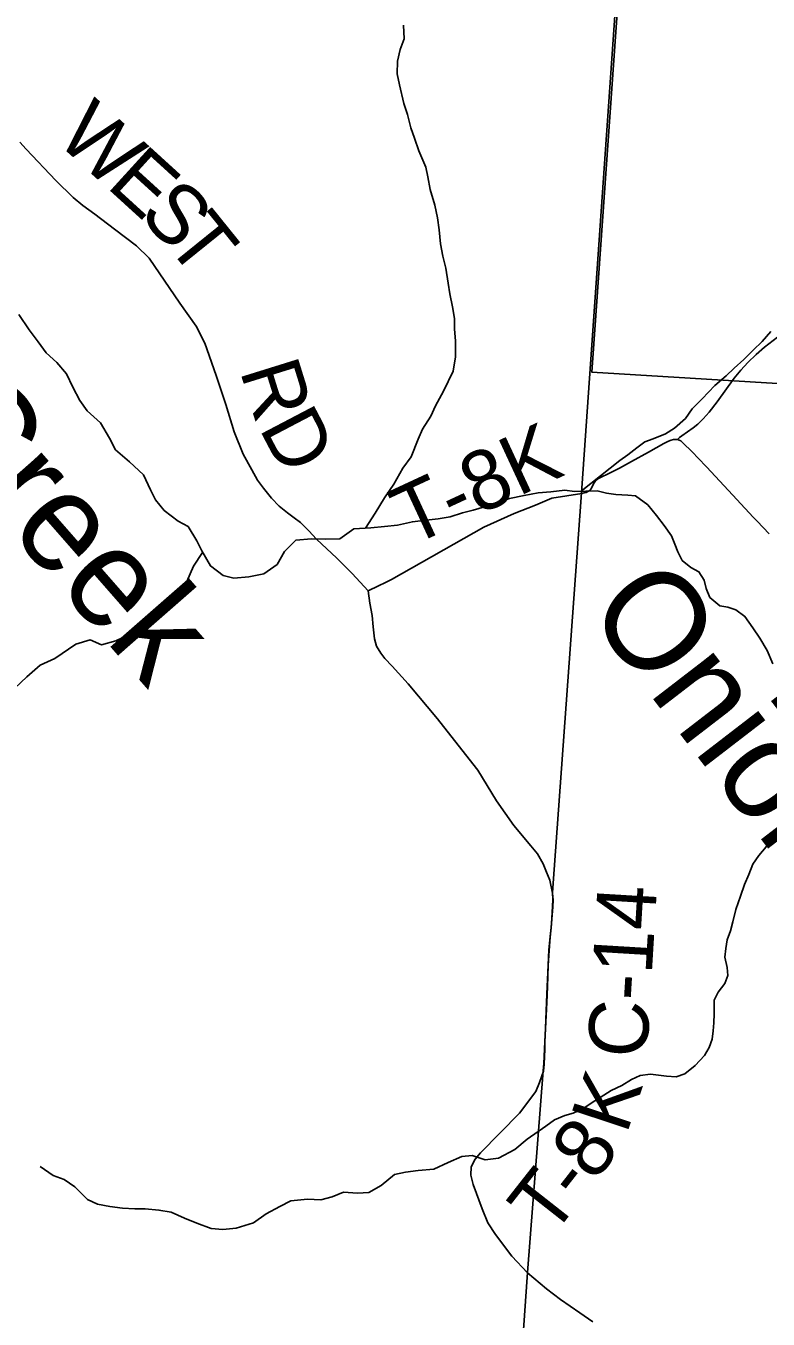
# Model space of a CAD drawing. Extents: x -8.2 to 34, y 0 to 22.
# Drawn here: x 6.05 to 6.76, y 18.744 to 19.98 of the extents above; entities that cross this region are included whole.
import ezdxf

# ---------------------------------------------------------------- set-up
doc = ezdxf.new("R2010")
doc.units = 0
for name, color, linetype in [('GM_X_Corporation', 7, 'Continuous'), ('GM_X_County_Road', 7, 'Continuous'), ('GM_X_County_Road_Text', 7, 'Continuous'), ('GM_X_Minor_River', 7, 'Continuous'), ('GM_X_Minor_River_Text', 7, 'Continuous'), ('GM_X_Township_Road', 7, 'Continuous'), ('GM_X_Township_Road_Text', 7, 'Continuous'), ('GM_X_Township_Text', 7, 'Continuous')]:
    doc.layers.add(name, color=color, linetype=linetype)

msp = doc.modelspace()

# ---------------------------------------------------------------- linework, layer by layer
at = {"layer": 'GM_X_Corporation'}
msp.add_lwpolyline([(6.4774, 18.0203), (6.488, 18.1752), (6.5242, 18.7061), (6.5297, 18.7882), (6.5448, 18.981), (6.5455, 18.9878), (6.5461, 19.0017), (6.5463, 19.009), (6.5469, 19.0218), (6.548, 19.0467), (6.5487, 19.0617), (6.5495, 19.0821), (6.5503, 19.0966), (6.5514, 19.1092), (6.5523, 19.118), (6.5529, 19.1264), (6.5537, 19.1382), (6.5541, 19.1447), (6.5536, 19.1514), (6.5814, 19.5334), (6.6608, 20.6695), (6.6768, 20.9), (2.1, 20.9), (2.1, 14.1)], dxfattribs=at)
msp.add_lwpolyline([(6.6629, 20.6653), (7.6877, 20.6096), (7.6147, 19.5864), (6.5914, 19.6487)], close=True, dxfattribs=at)
at = {"layer": 'GM_X_County_Road'}
for points in [[(6.0444, 19.8687), (6.0505, 19.8619), (6.0787, 19.832), (6.0954, 19.8159), (6.1045, 19.8081), (6.116, 19.7999), (6.135, 19.7855), (6.1558, 19.7696), (6.168, 19.7577), (6.1973, 19.7147), (6.2131, 19.6929), (6.2212, 19.6764), (6.232, 19.6455), (6.2415, 19.618), (6.2493, 19.5919), (6.2578, 19.5703), (6.2661, 19.5553), (6.2718, 19.5456), (6.2773, 19.5379), (6.2851, 19.5282), (6.2925, 19.5208), (6.3004, 19.5142), (6.3067, 19.5096), (6.3127, 19.5051), (6.3207, 19.4971), (6.3281, 19.489), (6.3476, 19.471), (6.3622, 19.4564), (6.3774, 19.4397), (6.3789, 19.428), (6.3813, 19.4162), (6.3823, 19.4052), (6.3834, 19.394), (6.3855, 19.387), (6.3897, 19.3802), (6.3933, 19.3751), (6.4003, 19.3679), (6.4158, 19.3508), (6.4439, 19.3173), (6.467, 19.2879), (6.4822, 19.2684), (6.5002, 19.239), (6.5166, 19.2155), (6.5329, 19.196), (6.5392, 19.1884), (6.5449, 19.1788), (6.5481, 19.171), (6.5513, 19.1632), (6.5538, 19.1509)], [(6.5538, 19.1509), (6.5543, 19.1442), (6.5539, 19.1377), (6.5532, 19.1259), (6.5525, 19.1175), (6.5516, 19.1087), (6.5505, 19.0961), (6.5497, 19.0816), (6.5489, 19.0612), (6.5482, 19.0462), (6.5471, 19.0213), (6.5465, 19.0084), (6.5463, 19.0012), (6.5457, 18.9873), (6.545, 18.9805)], [(6.5299, 18.7877), (6.5481, 18.7726), (6.5613, 18.7624), (6.5798, 18.7497), (6.5924, 18.741)]]:
    msp.add_lwpolyline(points, dxfattribs=at)
at = {"layer": 'GM_X_Minor_River'}
for points in [[(6.375, 19.4998), (6.3841, 19.5141), (6.3932, 19.5286), (6.4019, 19.5418), (6.4106, 19.557), (6.4185, 19.568), (6.4253, 19.5847), (6.4295, 19.5942), (6.4374, 19.6067), (6.4419, 19.6166), (6.4495, 19.6306), (6.4586, 19.6496), (6.4608, 19.6633), (6.4608, 19.6784), (6.46, 19.6902), (6.46, 19.7001), (6.4581, 19.7114), (6.4555, 19.7236), (6.4539, 19.7338), (6.4516, 19.7482), (6.449, 19.7596), (6.4467, 19.7714), (6.4452, 19.785), (6.4436, 19.7964), (6.4413, 19.8085), (6.4368, 19.8233), (6.4345, 19.8355), (6.4326, 19.8449), (6.4258, 19.8605), (6.4216, 19.8726), (6.4182, 19.8825), (6.4151, 19.895), (6.4117, 19.9056), (6.4075, 19.9235), (6.4052, 19.9341), (6.4056, 19.9462), (6.4079, 19.9572), (6.412, 19.9675), (6.4112, 19.9804)], [(6.0435, 19.704), (6.0534, 19.6892), (6.0621, 19.6779), (6.0697, 19.6672), (6.0799, 19.6581), (6.089, 19.6471), (6.0951, 19.6343), (6.1019, 19.6217), (6.1087, 19.6119), (6.1216, 19.6005), (6.1303, 19.5857), (6.136, 19.5747), (6.1493, 19.563), (6.1626, 19.5505), (6.1694, 19.5364), (6.174, 19.5266), (6.1823, 19.5167), (6.1959, 19.5065), (6.2054, 19.5012), (6.2138, 19.4875), (6.2183, 19.478), (6.2267, 19.4636), (6.2388, 19.4545), (6.249, 19.4519), (6.2634, 19.453)], [(6.5812, 19.5349), (6.6181, 19.5643), (6.6257, 19.5697), (6.6344, 19.5765), (6.642, 19.5823), (6.65, 19.585), (6.6617, 19.59), (6.6704, 19.5953), (6.6807, 19.6045), (6.6871, 19.6136), (6.6969, 19.6232), (6.709, 19.6362), (6.7196, 19.6453), (6.7275, 19.6526), (6.7366, 19.661), (6.7457, 19.6698), (6.754, 19.6782), (6.7623, 19.6877)], [(6.2634, 19.453), (6.2778, 19.4561), (6.2903, 19.4648), (6.2975, 19.4773), (6.3084, 19.4883), (6.3232, 19.4895), (6.3368, 19.4891), (6.3505, 19.4895), (6.3637, 19.499), (6.38, 19.5001), (6.3932, 19.5012), (6.4054, 19.5024), (6.4197, 19.5058), (6.433, 19.5073), (6.4443, 19.5085), (6.4557, 19.5104), (6.4678, 19.5142), (6.478, 19.5168), (6.4962, 19.5222), (6.5125, 19.5279), (6.5265, 19.5309), (6.5401, 19.5336), (6.5522, 19.5343), (6.5655, 19.5359), (6.5747, 19.5347)], [(6.5747, 19.5347), (6.5963, 19.5353), (6.6054, 19.5331), (6.6142, 19.532), (6.6256, 19.5313), (6.6332, 19.5306), (6.645, 19.5219), (6.6531, 19.5117), (6.6603, 19.5023), (6.6676, 19.4924), (6.6707, 19.4845), (6.6734, 19.4769), (6.6776, 19.4689), (6.686, 19.4621), (6.6937, 19.458), (6.6987, 19.4501), (6.7006, 19.4421), (6.7041, 19.4334), (6.7136, 19.4255), (6.7212, 19.424), (6.7289, 19.4217), (6.7376, 19.4153), (6.7453, 19.4044), (6.7518, 19.3945), (6.7588, 19.3828), (6.7645, 19.3699)], [(6.2192, 19.4765), (6.2104, 19.4632), (6.204, 19.4488), (6.1926, 19.4355), (6.1862, 19.4215), (6.1733, 19.4109), (6.1627, 19.4044), (6.1495, 19.3983), (6.1363, 19.3919), (6.1226, 19.3881), (6.1116, 19.393), (6.098, 19.3888), (6.078, 19.3752), (6.064, 19.3687), (6.0511, 19.3577), (6.0397, 19.3467)], [(6.7602, 19.2036), (6.7579, 19.1952), (6.7511, 19.1868), (6.7451, 19.1784), (6.7414, 19.1686), (6.7372, 19.159), (6.7335, 19.148), (6.729, 19.1351), (6.726, 19.1233), (6.7238, 19.1149), (6.7208, 19.1062), (6.7193, 19.0978), (6.7186, 19.0895), (6.7206, 19.0796), (6.7214, 19.072), (6.7184, 19.0644), (6.712, 19.056), (6.7082, 19.0484), (6.7083, 19.0355), (6.708, 19.0267), (6.7073, 19.0191), (6.7065, 19.0112), (6.7035, 19.0032), (6.699, 18.9956), (6.69, 18.986), (6.6801, 18.978), (6.6718, 18.9753), (6.6626, 18.976), (6.655, 18.9767), (6.6474, 18.9778), (6.6375, 18.9766), (6.6292, 18.9728), (6.6201, 18.967), (6.6099, 18.9621), (6.5993, 18.9555), (6.5917, 18.9506), (6.5837, 18.9452), (6.5735, 18.9406), (6.5655, 18.9383), (6.5557, 18.934), (6.5473, 18.9279), (6.5296, 18.9156)], [(6.5296, 18.9156), (6.5177, 18.9057), (6.5022, 18.8974), (6.4894, 18.8959), (6.4769, 18.9), (6.467, 18.8989), (6.4538, 18.8932), (6.4401, 18.8871), (6.4254, 18.8856), (6.4133, 18.8841), (6.4027, 18.8818), (6.3898, 18.8712), (6.3781, 18.8647), (6.3671, 18.8639), (6.3538, 18.8651), (6.3429, 18.8605), (6.3323, 18.8575), (6.3194, 18.8582), (6.3035, 18.8567), (6.2929, 18.8514), (6.28, 18.8442), (6.2679, 18.8358), (6.2513, 18.8305), (6.2384, 18.8294), (6.2274, 18.8301), (6.2138, 18.8354), (6.202, 18.84), (6.1891, 18.8457), (6.1774, 18.8479), (6.1641, 18.8491), (6.1543, 18.8491), (6.1426, 18.8498), (6.1304, 18.8513), (6.1187, 18.8536), (6.1092, 18.8578), (6.0971, 18.8699), (6.0869, 18.8771), (6.0763, 18.8809), (6.0638, 18.8896)]]:
    msp.add_lwpolyline(points, dxfattribs=at)
at = {"layer": 'GM_X_Township_Road'}
for points in [[(6.6731, 19.5843), (6.6751, 19.5862), (6.6775, 19.588), (6.6883, 19.5956), (6.6927, 19.5991), (6.6979, 19.6041), (6.7035, 19.6104), (6.7111, 19.6203), (6.7275, 19.6429), (6.7337, 19.6506), (6.7404, 19.658), (6.7485, 19.6657), (6.7565, 19.6726), (6.7687, 19.6822)], [(6.5816, 19.5329), (6.584, 19.5333), (6.5858, 19.5338), (6.5876, 19.5346), (6.5893, 19.5357), (6.5903, 19.5369), (6.5935, 19.5429), (6.5949, 19.545), (6.5969, 19.5468), (6.6002, 19.5485), (6.607, 19.5517), (6.6176, 19.5571), (6.6293, 19.5634), (6.6456, 19.5724), (6.6602, 19.5807), (6.6646, 19.5829), (6.6671, 19.5839), (6.6694, 19.5843), (6.6718, 19.5845), (6.6731, 19.5843), (6.6747, 19.5838), (6.6763, 19.5832), (6.6778, 19.582), (6.6879, 19.5719), (6.6926, 19.567), (6.7012, 19.5581), (6.7299, 19.527), (6.7456, 19.5103), (6.7495, 19.5063), (6.7551, 19.5004), (6.761, 19.4941)], [(6.3774, 19.4397), (6.3872, 19.4444), (6.394, 19.4477), (6.3999, 19.4505), (6.4882, 19.5007), (6.5172, 19.5136), (6.5373, 19.5216), (6.553, 19.5282), (6.5816, 19.5329)], [(6.5299, 18.7877), (6.5149, 18.8039), (6.4992, 18.8246), (6.492, 18.8356), (6.4864, 18.8491), (6.4777, 18.8722), (6.4757, 18.8812), (6.476, 18.8892), (6.4799, 18.8966), (6.4848, 18.9025), (6.5223, 18.9404), (6.5379, 18.9612), (6.5413, 18.9697), (6.545, 18.9805)]]:
    msp.add_lwpolyline(points, dxfattribs=at)
at = {"layer": 'GM_X_Township_Text'}
msp.add_lwpolyline([(6.6768, 20.9), (6.6608, 20.6695), (6.5814, 19.5334), (6.5536, 19.1514), (6.5541, 19.1447), (6.5537, 19.1382), (6.5529, 19.1264), (6.5523, 19.118), (6.5514, 19.1092), (6.5503, 19.0966), (6.5495, 19.0821), (6.5487, 19.0617), (6.548, 19.0467), (6.5469, 19.0218), (6.5463, 19.009), (6.5461, 19.0017), (6.5455, 18.9878), (6.5448, 18.981), (6.5297, 18.7882), (6.5242, 18.7061), (6.488, 18.1752), (6.4774, 18.0203)], dxfattribs=at)

# ---------------------------------------------------------------- texts
at = {"layer": 'GM_X_County_Road_Text'}
for s, height, rotation, p in [('W', 0.0568, 317.8359, (6.0773, 19.8705)), ('E', 0.0568, 317.6675, (6.1261, 19.8263)), ('S', 0.0568, 314.58, (6.1569, 19.7983)), ('T', 0.0568, 308.882, (6.1828, 19.7721)), ('R', 0.0568, 287.2858, (6.2545, 19.6504)), ('D', 0.0568, 297.6697, (6.2726, 19.5956)), ('C-14', 0.05682, 86.5725, (6.6438, 18.9923))]:
    msp.add_text(s, height=height, rotation=rotation, dxfattribs=at).set_placement(p)
at = {"layer": 'GM_X_Minor_River_Text'}
for s, rotation, p in [('Creek', 311.193, (5.9446, 19.5992)), ('Onion', 307.6002, (6.5845, 19.4211))]:
    msp.add_text(s, height=0.0947, rotation=rotation, dxfattribs=at).set_placement(p)
at = {"layer": 'GM_X_Township_Road_Text'}
for s, height, rotation, p in [('T-8K', 0.05682, 24.8977, (6.4175, 19.4816)), ('K', 0.0568, 71.6726, (6.6245, 18.9193)), ('8', 0.0568, 53.0228, (6.5941, 18.8736)), ('T', 0.0568, 51.8408, (6.5527, 18.8207)), ('-', 0.0568, 52.0447, (6.5791, 18.8543))]:
    msp.add_text(s, height=height, rotation=rotation, dxfattribs=at).set_placement(p)

doc.saveas('drawing.dxf')
